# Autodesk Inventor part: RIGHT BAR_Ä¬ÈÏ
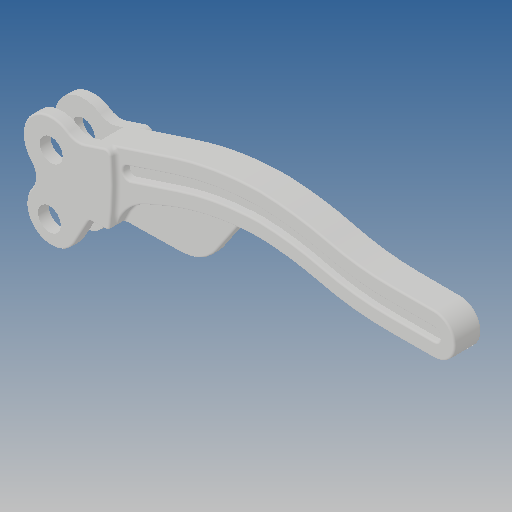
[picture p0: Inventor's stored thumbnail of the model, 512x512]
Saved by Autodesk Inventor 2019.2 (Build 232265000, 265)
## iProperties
Created: 2010-06
Part Number: RIGHT BAR_Ä¬ÈÏ
Material: Ogólny
Document SubType Name: Modeling
Designer: CADENGINEERING4
Density: 1 g/cm^3
Appearance: Domyślna
Author: CADENGINEERING4
Revision Number: ÈÎºÎ
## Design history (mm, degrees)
feature "NONE"
node "Bryła1"
